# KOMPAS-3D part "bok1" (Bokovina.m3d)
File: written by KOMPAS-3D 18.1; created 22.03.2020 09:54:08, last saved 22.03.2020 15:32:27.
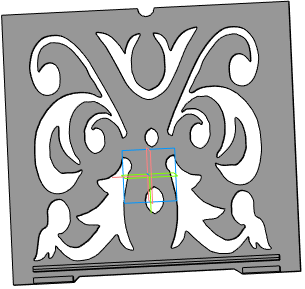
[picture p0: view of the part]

Document properties: Полное имя файла: C:\Users\windw\Desktop\shkatilka1\bez petli\Измененная\Bokovina.m3d

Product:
- Part/product: bok1
    Масса: 2.45203

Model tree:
1. Эскиз:1
2. Элемент выдавливания:1
     Расстояние 1 = 6
3. Эскиз:2  (with: Элемент выдавливания:1)
4. Элемент выдавливания:2
     Расстояние 1 = 10
5. Скругление:2  (with: Элемент выдавливания:2)
     Радиус = 3
6. Скругление:3  (with: Элемент выдавливания:1)
     Радиус = 1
